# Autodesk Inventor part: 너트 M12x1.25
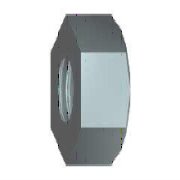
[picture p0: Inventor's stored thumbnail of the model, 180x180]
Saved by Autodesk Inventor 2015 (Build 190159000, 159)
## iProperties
IsCustomPart: 0
Created: 2015-12
Part Number: 너트 M12x1.25
Material: 스테인리스강
Description: 6각 너트
Document SubType Name: Modeling
Standard: KS B 1012
Designer: mdu
Standards Organization: KS
Language: ko-KR
Size Designation: M12x1.25
Categories: <MemberInstance><Categories><Category DisplayName="조임쇠" InternalName="e4da775c-781d-43d5-af7c-5136215cf5a6" Mnemonic="FSTN"><Category DisplayName="너트" InternalN
Density: 8.08 g/cm^3
Appearance: 반광택
Author: mdu
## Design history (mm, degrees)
sketch "스케치1"
  geometry: L1 (10.97, 0)-(5.485, -9.5); L2 (5.485, -9.5)-(-5.485, -9.5); L3 (-5.485, -9.5)-(-10.97, 0); L4 (-10.97, 0)-(-5.485, 9.5); L5 (-5.485, 9.5)-(5.485, 9.5); L6 (5.485, 9.5)-(10.97, 0); 2 further points
  constraints: 12 end point, 1 coincident, 1 horizontal, 11 other
  dimensions: "d0" = 21.93931 distance of L1.start L3.end (= 1.1547 x SW)
extrude "본체" new body sketch "스케치1" distance "d1" = 10 (= KOH); taper "d2" = 0 deg
sketch "스케치2"
  geometry: 1 further point
hole "스레드" sketch "스케치2" diameter "d6" = 10.647; stored, may be unused: countersink angle "d10" = 82 deg, drill point angle "d12" = 118 deg; dims "d7" = 12.7, "d8" = 9.525, "d9" = 6.35, "d11" = 19.05
sketch "스케치3"
  geometry: L1 (0, 10.97)-(10, 10.97) reference; L2 (10, 5.485)-(10, 10.97) reference; L3 (-2, 0)-(12, 0) reference; L4 (9.151, 10.97)-(10, 9.5)
  constraints: 2 end point, 2 point on line
  dimensions: "d3" = 19 diameter of L4.end L3 (= SW01); "d4" = 30 deg angle of L2 L4 (= ANG2)
revolve "모따기3" sketch "스케치3" stored, may be unused: angle "d5" = 90 deg
workaxis "Work Axis1"
workplane "Work Plane1"
body "Solid1"
chamfer "모따기1" distance "d13" = 0.67658 (= -0.5 x GD1 + 0.5 x NND); stored, may be unused: angle "d14" = 30 deg, second distance "d21" = 0.67658 (= -0.5 x GD1 + 0.5 x NND)
chamfer "모따기2" distance "d15" = 0.67658 (= -0.5 x GD1 + 0.5 x NND); stored, may be unused: angle "d16" = 30 deg, second distance "d22" = 0.67658 (= -0.5 x GD1 + 0.5 x NND)
other parameters: "ANG2" = 30 deg [user parameter; used in 1 equation term], "NND" = 12 [user parameter; used in 4 equation terms], "KOH" = 10 [user parameter; used in 1 equation term], "SW" = 19 [user parameter; used in 3 equation terms], "SW01" = 19 (= SW) [user parameter; used in 1 equation term], "GD1" = 10.64684 (computed from THREADDIA, PTC, TOA) [user parameter; used in 4 equation terms], "d19" = 0, "d20" = 0, "d24" = 0, "d25" = 0, "GUL" = 0.67658 (= 0.541266 x PTC) [user parameter], "TPU" = 8 (computed from PTC) [user parameter], "TOA" = 30 deg [user parameter; used in 1 equation term], "PTC" = 1.25 [user parameter; used in 4 equation terms], "E0" = 21.945 (= 1.155 x SW) [user parameter], "THREADDIA" = 12 [user parameter; used in 1 equation term], "GAL" = 0.67658 (= 0.541266 x PTC) [user parameter]
